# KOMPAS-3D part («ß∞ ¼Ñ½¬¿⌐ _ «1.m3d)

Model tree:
1. Эскиз:1
2. Операция выдавливания:1
     Расстояние 1 = 0.5; Расстояние 2 = 0.3
3. Эскиз:2
4. Операция выдавливания:2
     Расстояние 1 = 37; Расстояние 2 = 0.3
5. Скругление:1
     Радиус = 0.5
6. Скругление:2
     Радиус = 0.1
7. Скругление:3
     Радиус = 0.1
